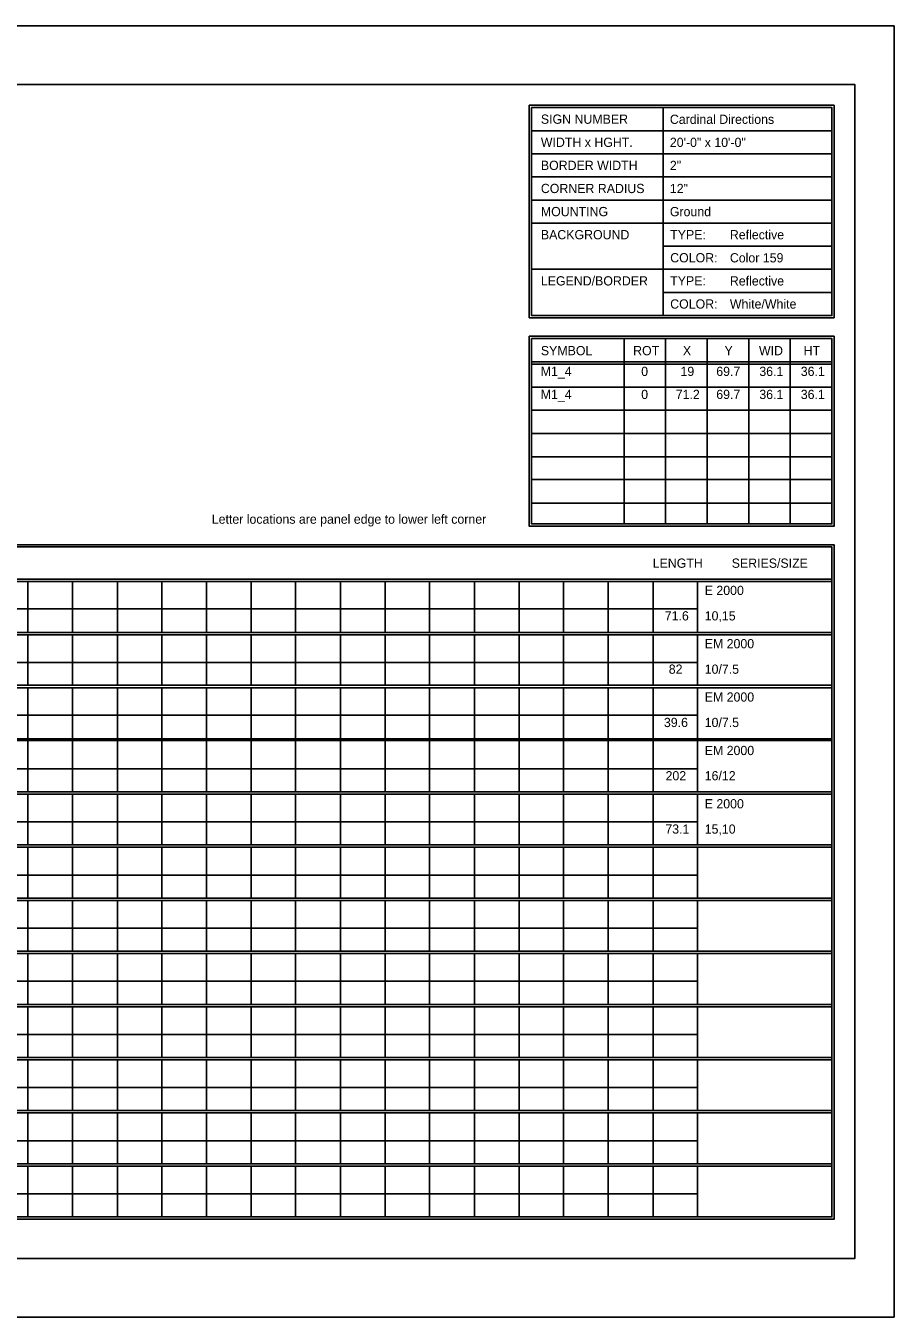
# Model space of a CAD drawing. Extents: x 1806251 to 1809821, y 414895 to 422886.
# Drawn here: x 1809679.34 to 1809684.89, y 415035.97 to 415044.23 of the extents above; entities that cross this region are included whole.
import ezdxf

# ---------------------------------------------------------------- set-up
doc = ezdxf.new("R2010")
doc.units = 0
doc.layers.add('GSSHT', color=7, linetype='Continuous')

msp = doc.modelspace()

# ---------------------------------------------------------------- linework, layer by layer
at = {"layer": 'GSSHT'}
for p, q in [((1809672.1349, 415044.2262), (1809684.8891, 415044.2262)), ((1809684.8891, 415044.2262), (1809684.8891, 415035.9725)), ((1809683.4126, 415043.7035), (1809683.4126, 415042.3747)), ((1809682.571, 415043.5559), (1809684.4905, 415043.5559)), ((1809682.571, 415043.4082), (1809684.4905, 415043.4082)), ((1809682.571, 415043.2606), (1809684.4905, 415043.2606)), ((1809682.571, 415043.1129), (1809684.4905, 415043.1129)), ((1809682.571, 415042.9653), (1809684.4905, 415042.9653)), ((1809683.4126, 415042.8176), (1809684.4905, 415042.8176)), ((1809682.571, 415042.67), (1809684.4905, 415042.67)), ((1809683.4126, 415042.5223), (1809684.4905, 415042.5223)), ((1809683.1616, 415042.227), (1809683.1616, 415041.0428)), ((1809683.4274, 415042.227), (1809683.4274, 415041.0428)), ((1809683.6931, 415042.227), (1809683.6931, 415041.0428)), ((1809683.9589, 415042.227), (1809683.9589, 415041.0428)), ((1809684.2247, 415042.227), (1809684.2247, 415041.0428)), ((1809682.571, 415042.0794), (1809684.4905, 415042.0794)), ((1809682.571, 415042.0646), (1809684.4905, 415042.0646)), ((1809682.571, 415041.9169), (1809684.4905, 415041.9169)), ((1809682.571, 415041.7693), (1809684.4905, 415041.7693)), ((1809682.571, 415041.6216), (1809684.4905, 415041.6216)), ((1809682.571, 415041.471), (1809684.4905, 415041.471)), ((1809682.571, 415041.3263), (1809684.4905, 415041.3263)), ((1809682.571, 415041.1757), (1809684.4905, 415041.1757)), ((1809672.7816, 415040.6885), (1809684.4905, 415040.6885)), ((1809672.7816, 415040.6737), (1809684.4905, 415040.6737)), ((1809679.3492, 415040.6737), (1809679.3492, 415040.3489)), ((1809679.6357, 415040.6737), (1809679.6357, 415040.3489)), ((1809679.9221, 415040.6737), (1809679.9221, 415040.3489)), ((1809680.2056, 415040.6737), (1809680.2056, 415040.3489)), ((1809680.492, 415040.6737), (1809680.492, 415040.3489)), ((1809680.7785, 415040.6737), (1809680.7785, 415040.3489)), ((1809681.062, 415040.6737), (1809681.062, 415040.3489)), ((1809681.3484, 415040.6737), (1809681.3484, 415040.3489)), ((1809681.6349, 415040.6737), (1809681.6349, 415040.3489)), ((1809681.9184, 415040.6737), (1809681.9184, 415040.3489)), ((1809682.2048, 415040.6737), (1809682.2048, 415040.3489)), ((1809682.4913, 415040.6737), (1809682.4913, 415040.3489)), ((1809682.7747, 415040.6737), (1809682.7747, 415040.3489)), ((1809683.0612, 415040.6737), (1809683.0612, 415040.3489)), ((1809683.3476, 415040.6737), (1809683.3476, 415040.3489)), ((1809683.6311, 415040.6737), (1809683.6311, 415040.3489)), ((1809672.7816, 415040.4995), (1809683.6311, 415040.4995)), ((1809672.7816, 415040.3489), (1809684.4905, 415040.3489)), ((1809672.7816, 415040.3341), (1809684.4905, 415040.3341)), ((1809679.3492, 415040.3341), (1809679.3492, 415040.0122)), ((1809679.6357, 415040.3341), (1809679.6357, 415040.0122)), ((1809679.9221, 415040.3341), (1809679.9221, 415040.0122)), ((1809680.2056, 415040.3341), (1809680.2056, 415040.0122)), ((1809680.492, 415040.3341), (1809680.492, 415040.0122)), ((1809680.7785, 415040.3341), (1809680.7785, 415040.0122)), ((1809681.062, 415040.3341), (1809681.062, 415040.0122)), ((1809681.3484, 415040.3341), (1809681.3484, 415040.0122)), ((1809681.6349, 415040.3341), (1809681.6349, 415040.0122)), ((1809681.9184, 415040.3341), (1809681.9184, 415040.0122)), ((1809682.2048, 415040.3341), (1809682.2048, 415040.0122)), ((1809682.4913, 415040.3341), (1809682.4913, 415040.0122)), ((1809682.7747, 415040.3341), (1809682.7747, 415040.0122)), ((1809683.0612, 415040.3341), (1809683.0612, 415040.0122)), ((1809683.3476, 415040.3341), (1809683.3476, 415040.0122)), ((1809683.6311, 415040.3341), (1809683.6311, 415040.0122)), ((1809672.7816, 415040.1569), (1809683.6311, 415040.1569)), ((1809672.7816, 415040.0122), (1809684.4905, 415040.0122)), ((1809672.7816, 415039.9945), (1809684.4905, 415039.9945)), ((1809679.3492, 415039.9945), (1809679.3492, 415039.6697)), ((1809679.6357, 415039.9945), (1809679.6357, 415039.6697)), ((1809679.9221, 415039.9945), (1809679.9221, 415039.6697)), ((1809680.2056, 415039.9945), (1809680.2056, 415039.6697)), ((1809680.492, 415039.9945), (1809680.492, 415039.6697)), ((1809680.7785, 415039.9945), (1809680.7785, 415039.6697)), ((1809681.062, 415039.9945), (1809681.062, 415039.6697)), ((1809681.3484, 415039.9945), (1809681.3484, 415039.6697)), ((1809681.6349, 415039.9945), (1809681.6349, 415039.6697)), ((1809681.9184, 415039.9945), (1809681.9184, 415039.6697)), ((1809682.2048, 415039.9945), (1809682.2048, 415039.6697)), ((1809682.4913, 415039.9945), (1809682.4913, 415039.6697)), ((1809682.7747, 415039.9945), (1809682.7747, 415039.6697)), ((1809683.0612, 415039.9945), (1809683.0612, 415039.6697)), ((1809683.3476, 415039.9945), (1809683.3476, 415039.6697)), ((1809683.6311, 415039.9945), (1809683.6311, 415039.6697)), ((1809672.7816, 415039.8203), (1809683.6311, 415039.8203)), ((1809672.7816, 415039.6697), (1809684.4905, 415039.6697)), ((1809672.7816, 415039.6579), (1809684.4905, 415039.6579)), ((1809679.3492, 415039.6579), (1809679.3492, 415039.3301)), ((1809679.6357, 415039.6579), (1809679.6357, 415039.3301)), ((1809679.9221, 415039.6579), (1809679.9221, 415039.3301)), ((1809680.2056, 415039.6579), (1809680.2056, 415039.3301)), ((1809680.492, 415039.6579), (1809680.492, 415039.3301)), ((1809680.7785, 415039.6579), (1809680.7785, 415039.3301)), ((1809681.062, 415039.6579), (1809681.062, 415039.3301)), ((1809681.3484, 415039.6579), (1809681.3484, 415039.3301)), ((1809681.6349, 415039.6579), (1809681.6349, 415039.3301)), ((1809681.9184, 415039.6579), (1809681.9184, 415039.3301)), ((1809682.2048, 415039.6579), (1809682.2048, 415039.3301)), ((1809682.4913, 415039.6579), (1809682.4913, 415039.3301)), ((1809682.7747, 415039.6579), (1809682.7747, 415039.3301)), ((1809683.0612, 415039.6579), (1809683.0612, 415039.3301)), ((1809683.3476, 415039.6579), (1809683.3476, 415039.3301)), ((1809683.6311, 415039.6579), (1809683.6311, 415039.3301)), ((1809672.7816, 415039.4777), (1809683.6311, 415039.4777)), ((1809672.7816, 415039.3301), (1809684.4905, 415039.3301)), ((1809672.7816, 415039.3153), (1809684.4905, 415039.3153)), ((1809679.3492, 415039.3153), (1809679.3492, 415038.9905)), ((1809679.6357, 415039.3153), (1809679.6357, 415038.9905)), ((1809679.9221, 415039.3153), (1809679.9221, 415038.9905)), ((1809680.2056, 415039.3153), (1809680.2056, 415038.9905)), ((1809680.492, 415039.3153), (1809680.492, 415038.9905)), ((1809680.7785, 415039.3153), (1809680.7785, 415038.9905)), ((1809681.062, 415039.3153), (1809681.062, 415038.9905)), ((1809681.3484, 415039.3153), (1809681.3484, 415038.9905)), ((1809681.6349, 415039.3153), (1809681.6349, 415038.9905)), ((1809681.9184, 415039.3153), (1809681.9184, 415038.9905)), ((1809682.2048, 415039.3153), (1809682.2048, 415038.9905)), ((1809682.4913, 415039.3153), (1809682.4913, 415038.9905)), ((1809682.7747, 415039.3153), (1809682.7747, 415038.9905)), ((1809683.0612, 415039.3153), (1809683.0612, 415038.9905)), ((1809683.3476, 415039.3153), (1809683.3476, 415038.9905)), ((1809683.6311, 415039.3153), (1809683.6311, 415038.9905)), ((1809672.7816, 415039.1381), (1809683.6311, 415039.1381)), ((1809672.7816, 415038.9905), (1809684.4905, 415038.9905)), ((1809672.7816, 415038.9757), (1809684.4905, 415038.9757)), ((1809679.3492, 415038.9757), (1809679.3492, 415038.6509)), ((1809679.6357, 415038.9757), (1809679.6357, 415038.6509)), ((1809679.9221, 415038.9757), (1809679.9221, 415038.6509)), ((1809680.2056, 415038.9757), (1809680.2056, 415038.6509)), ((1809680.492, 415038.9757), (1809680.492, 415038.6509)), ((1809680.7785, 415038.9757), (1809680.7785, 415038.6509)), ((1809681.062, 415038.9757), (1809681.062, 415038.6509)), ((1809681.3484, 415038.9757), (1809681.3484, 415038.6509)), ((1809681.6349, 415038.9757), (1809681.6349, 415038.6509)), ((1809681.9184, 415038.9757), (1809681.9184, 415038.6509)), ((1809682.2048, 415038.9757), (1809682.2048, 415038.6509)), ((1809682.4913, 415038.9757), (1809682.4913, 415038.6509)), ((1809682.7747, 415038.9757), (1809682.7747, 415038.6509)), ((1809683.0612, 415038.9757), (1809683.0612, 415038.6509)), ((1809683.3476, 415038.9757), (1809683.3476, 415038.6509)), ((1809683.6311, 415038.9757), (1809683.6311, 415038.6509)), ((1809672.7816, 415038.7985), (1809683.6311, 415038.7985)), ((1809672.7816, 415038.6509), (1809684.4905, 415038.6509)), ((1809672.7816, 415038.6361), (1809684.4905, 415038.6361)), ((1809679.3492, 415038.6361), (1809679.3492, 415038.3113)), ((1809679.6357, 415038.6361), (1809679.6357, 415038.3113)), ((1809679.9221, 415038.6361), (1809679.9221, 415038.3113)), ((1809680.2056, 415038.6361), (1809680.2056, 415038.3113)), ((1809680.492, 415038.6361), (1809680.492, 415038.3113)), ((1809680.7785, 415038.6361), (1809680.7785, 415038.3113)), ((1809681.062, 415038.6361), (1809681.062, 415038.3113)), ((1809681.3484, 415038.6361), (1809681.3484, 415038.3113)), ((1809681.6349, 415038.6361), (1809681.6349, 415038.3113)), ((1809681.9184, 415038.6361), (1809681.9184, 415038.3113)), ((1809682.2048, 415038.6361), (1809682.2048, 415038.3113)), ((1809682.4913, 415038.6361), (1809682.4913, 415038.3113)), ((1809682.7747, 415038.6361), (1809682.7747, 415038.3113)), ((1809683.0612, 415038.6361), (1809683.0612, 415038.3113)), ((1809683.3476, 415038.6361), (1809683.3476, 415038.3113)), ((1809683.6311, 415038.6361), (1809683.6311, 415038.3113)), ((1809672.7816, 415038.4589), (1809683.6311, 415038.4589)), ((1809672.7816, 415038.3113), (1809684.4905, 415038.3113)), ((1809672.7816, 415038.2965), (1809684.4905, 415038.2965)), ((1809679.3492, 415038.2965), (1809679.3492, 415037.9717)), ((1809679.6357, 415038.2965), (1809679.6357, 415037.9717)), ((1809679.9221, 415038.2965), (1809679.9221, 415037.9717)), ((1809680.2056, 415038.2965), (1809680.2056, 415037.9717)), ((1809680.492, 415038.2965), (1809680.492, 415037.9717)), ((1809680.7785, 415038.2965), (1809680.7785, 415037.9717)), ((1809681.062, 415038.2965), (1809681.062, 415037.9717)), ((1809681.3484, 415038.2965), (1809681.3484, 415037.9717)), ((1809681.6349, 415038.2965), (1809681.6349, 415037.9717)), ((1809681.9184, 415038.2965), (1809681.9184, 415037.9717)), ((1809682.2048, 415038.2965), (1809682.2048, 415037.9717)), ((1809682.4913, 415038.2965), (1809682.4913, 415037.9717)), ((1809682.7747, 415038.2965), (1809682.7747, 415037.9717)), ((1809683.0612, 415038.2965), (1809683.0612, 415037.9717)), ((1809683.3476, 415038.2965), (1809683.3476, 415037.9717)), ((1809683.6311, 415038.2965), (1809683.6311, 415037.9717)), ((1809672.7816, 415038.1193), (1809683.6311, 415038.1193)), ((1809672.7816, 415037.9717), (1809684.4905, 415037.9717)), ((1809672.7816, 415037.9569), (1809684.4905, 415037.9569)), ((1809679.3492, 415037.9569), (1809679.3492, 415037.6321)), ((1809679.6357, 415037.9569), (1809679.6357, 415037.6321)), ((1809679.9221, 415037.9569), (1809679.9221, 415037.6321)), ((1809680.2056, 415037.9569), (1809680.2056, 415037.6321)), ((1809680.492, 415037.9569), (1809680.492, 415037.6321)), ((1809680.7785, 415037.9569), (1809680.7785, 415037.6321)), ((1809681.062, 415037.9569), (1809681.062, 415037.6321)), ((1809681.3484, 415037.9569), (1809681.3484, 415037.6321)), ((1809681.6349, 415037.9569), (1809681.6349, 415037.6321)), ((1809681.9184, 415037.9569), (1809681.9184, 415037.6321)), ((1809682.2048, 415037.9569), (1809682.2048, 415037.6321)), ((1809682.4913, 415037.9569), (1809682.4913, 415037.6321)), ((1809682.7747, 415037.9569), (1809682.7747, 415037.6321)), ((1809683.0612, 415037.9569), (1809683.0612, 415037.6321)), ((1809683.3476, 415037.9569), (1809683.3476, 415037.6321)), ((1809683.6311, 415037.9569), (1809683.6311, 415037.6321)), ((1809672.7816, 415037.7797), (1809683.6311, 415037.7797)), ((1809672.7816, 415037.6321), (1809684.4905, 415037.6321)), ((1809672.7816, 415037.6173), (1809684.4905, 415037.6173)), ((1809679.3492, 415037.6173), (1809679.3492, 415037.2925)), ((1809679.6357, 415037.6173), (1809679.6357, 415037.2925)), ((1809679.9221, 415037.6173), (1809679.9221, 415037.2925)), ((1809680.2056, 415037.6173), (1809680.2056, 415037.2925)), ((1809680.492, 415037.6173), (1809680.492, 415037.2925)), ((1809680.7785, 415037.6173), (1809680.7785, 415037.2925)), ((1809681.062, 415037.6173), (1809681.062, 415037.2925)), ((1809681.3484, 415037.6173), (1809681.3484, 415037.2925)), ((1809681.6349, 415037.6173), (1809681.6349, 415037.2925)), ((1809681.9184, 415037.6173), (1809681.9184, 415037.2925)), ((1809682.2048, 415037.6173), (1809682.2048, 415037.2925)), ((1809682.4913, 415037.6173), (1809682.4913, 415037.2925)), ((1809682.7747, 415037.6173), (1809682.7747, 415037.2925)), ((1809683.0612, 415037.6173), (1809683.0612, 415037.2925)), ((1809683.3476, 415037.6173), (1809683.3476, 415037.2925)), ((1809683.6311, 415037.6173), (1809683.6311, 415037.2925)), ((1809672.7816, 415037.4401), (1809683.6311, 415037.4401)), ((1809672.7816, 415037.2925), (1809684.4905, 415037.2925)), ((1809672.7816, 415037.2777), (1809684.4905, 415037.2777)), ((1809679.3492, 415037.2777), (1809679.3492, 415036.9529)), ((1809679.6357, 415037.2777), (1809679.6357, 415036.9529)), ((1809679.9221, 415037.2777), (1809679.9221, 415036.9529)), ((1809680.2056, 415037.2777), (1809680.2056, 415036.9529)), ((1809680.492, 415037.2777), (1809680.492, 415036.9529)), ((1809680.7785, 415037.2777), (1809680.7785, 415036.9529)), ((1809681.062, 415037.2777), (1809681.062, 415036.9529)), ((1809681.3484, 415037.2777), (1809681.3484, 415036.9529)), ((1809681.6349, 415037.2777), (1809681.6349, 415036.9529)), ((1809681.9184, 415037.2777), (1809681.9184, 415036.9529)), ((1809682.2048, 415037.2777), (1809682.2048, 415036.9529)), ((1809682.4913, 415037.2777), (1809682.4913, 415036.9529)), ((1809682.7747, 415037.2777), (1809682.7747, 415036.9529)), ((1809683.0612, 415037.2777), (1809683.0612, 415036.9529)), ((1809683.3476, 415037.2777), (1809683.3476, 415036.9529)), ((1809683.6311, 415037.2777), (1809683.6311, 415036.9529)), ((1809672.7816, 415037.1005), (1809683.6311, 415037.1005)), ((1809672.7816, 415036.9529), (1809684.4905, 415036.9529)), ((1809672.7816, 415036.9381), (1809684.4905, 415036.9381)), ((1809679.3492, 415036.9381), (1809679.3492, 415036.6133)), ((1809679.6357, 415036.9381), (1809679.6357, 415036.6133)), ((1809679.9221, 415036.9381), (1809679.9221, 415036.6133)), ((1809680.2056, 415036.9381), (1809680.2056, 415036.6133)), ((1809680.492, 415036.9381), (1809680.492, 415036.6133)), ((1809680.7785, 415036.9381), (1809680.7785, 415036.6133)), ((1809681.062, 415036.9381), (1809681.062, 415036.6133)), ((1809681.3484, 415036.9381), (1809681.3484, 415036.6133)), ((1809681.6349, 415036.9381), (1809681.6349, 415036.6133)), ((1809681.9184, 415036.9381), (1809681.9184, 415036.6133)), ((1809682.2048, 415036.9381), (1809682.2048, 415036.6133)), ((1809682.4913, 415036.9381), (1809682.4913, 415036.6133)), ((1809682.7747, 415036.9381), (1809682.7747, 415036.6133)), ((1809683.0612, 415036.9381), (1809683.0612, 415036.6133)), ((1809683.3476, 415036.9381), (1809683.3476, 415036.6133)), ((1809683.6311, 415036.9381), (1809683.6311, 415036.6133)), ((1809672.7816, 415036.7609), (1809683.6311, 415036.7609)), ((1809684.8891, 415035.9725), (1809672.1349, 415035.9725))]:
    msp.add_line(p, q, dxfattribs=at)
for points in [[(1809672.634, 415043.8512), (1809684.6381, 415043.8512), (1809684.6381, 415036.3475), (1809672.634, 415036.3475)], [(1809682.5562, 415043.7183), (1809684.5052, 415043.7183), (1809684.5052, 415042.3599), (1809682.5562, 415042.3599)], [(1809682.571, 415043.7035), (1809684.4905, 415043.7035), (1809684.4905, 415042.3747), (1809682.571, 415042.3747)], [(1809682.5562, 415042.2418), (1809684.5052, 415042.2418), (1809684.5052, 415041.0281), (1809682.5562, 415041.0281)], [(1809682.571, 415042.227), (1809684.4905, 415042.227), (1809684.4905, 415041.0428), (1809682.571, 415041.0428)], [(1809672.7669, 415040.91), (1809684.5052, 415040.91), (1809684.5052, 415036.5985), (1809672.7669, 415036.5985)], [(1809672.7816, 415040.8952), (1809684.4905, 415040.8952), (1809684.4905, 415036.6133), (1809672.7816, 415036.6133)]]:
    msp.add_lwpolyline(points, close=True, dxfattribs=at)

# ---------------------------------------------------------------- texts
for s, height, p in [('SIGN NUMBER', 0.059055, (1809682.63, 415043.6002)), ('Cardinal Directions', 0.059025, (1809683.4549, 415043.5994)), ('WIDTH x HGHT.', 0.059055, (1809682.63, 415043.4525)), ('20\'-0" x 10\'-0"', 0.059025, (1809683.4549, 415043.4519)), ('BORDER WIDTH', 0.059055, (1809682.63, 415043.3049)), ('2"', 0.05903, (1809683.4549, 415043.3043)), ('CORNER RADIUS', 0.059055, (1809682.63, 415043.1572)), ('12"', 0.05903, (1809683.4549, 415043.1568)), ('MOUNTING', 0.05906, (1809682.63, 415043.0096)), ('Ground', 0.05903, (1809683.4549, 415043.0092)), ('BACKGROUND', 0.05906, (1809682.63, 415042.8619)), ('TYPE:', 0.05906, (1809683.4569, 415042.8619)), ('Reflective', 0.05903, (1809683.8386, 415042.8616)), ('COLOR:', 0.05906, (1809683.4569, 415042.7143)), ('Color 159', 0.05903, (1809683.8386, 415042.7141)), ('LEGEND/BORDER', 0.059055, (1809682.63, 415042.5666)), ('TYPE:', 0.05906, (1809683.4569, 415042.5666)), ('Reflective', 0.05903, (1809683.8386, 415042.5665)), ('COLOR:', 0.05906, (1809683.4569, 415042.419)), ('White/White', 0.059025, (1809683.8386, 415042.4189)), ('SYMBOL', 0.05906, (1809682.63, 415042.1207)), ('ROT', 0.05906, (1809683.22, 415042.1207)), ('X', 0.0591, (1809683.538, 415042.1207)), ('Y', 0.0591, (1809683.8041, 415042.1207)), ('WID', 0.05906, (1809684.0246, 415042.1207)), ('HT', 0.05906, (1809684.3102, 415042.1207)), ('M1_4', 0.05903, (1809682.6291, 415041.9881)), ('0', 0.059, (1809683.2716, 415041.9881)), ('19', 0.05903, (1809683.5228, 415041.9881)), ('69.7', 0.05903, (1809683.7515, 415041.9881)), ('36.1', 0.05903, (1809684.0268, 415041.9881)), ('36.1', 0.05903, (1809684.2919, 415041.9881)), ('M1_4', 0.05903, (1809682.6291, 415041.8409)), ('0', 0.059, (1809683.2716, 415041.8409)), ('71.2', 0.05903, (1809683.4923, 415041.8409)), ('69.7', 0.05903, (1809683.7515, 415041.8409)), ('36.1', 0.05903, (1809684.0268, 415041.8409)), ('36.1', 0.05903, (1809684.2919, 415041.8409)), ('Letter locations are panel edge to lower left corner', 0.059025, (1809680.5257, 415041.0437)), ('LENGTH', 0.05906, (1809683.345, 415040.7623)), ('SERIES/SIZE', 0.059061, (1809683.8502, 415040.7623)), ('E 2000', 0.05903, (1809683.6777, 415040.5883)), ('71.6', 0.05903, (1809683.4223, 415040.4257)), ('10,15', 0.05903, (1809683.6777, 415040.4257)), ('EM 2000', 0.05903, (1809683.6777, 415040.2476)), ('82', 0.05903, (1809683.4478, 415040.0849)), ('10/7.5', 0.05903, (1809683.6777, 415040.0849)), ('EM 2000', 0.05903, (1809683.6777, 415039.9068)), ('39.6', 0.05903, (1809683.4168, 415039.7442)), ('10/7.5', 0.05903, (1809683.6777, 415039.7442)), ('EM 2000', 0.05903, (1809683.6777, 415039.5651)), ('202', 0.05903, (1809683.4273, 415039.4035)), ('16/12', 0.05903, (1809683.6777, 415039.4035)), ('E 2000', 0.05903, (1809683.6777, 415039.2244)), ('73.1', 0.05903, (1809683.4258, 415039.0627)), ('15,10', 0.05903, (1809683.6777, 415039.0627))]:
    msp.add_text(s, height=height, dxfattribs=at).set_placement(p)

doc.saveas('drawing.dxf')
